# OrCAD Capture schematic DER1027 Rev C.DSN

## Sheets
1 PAGE2: size B
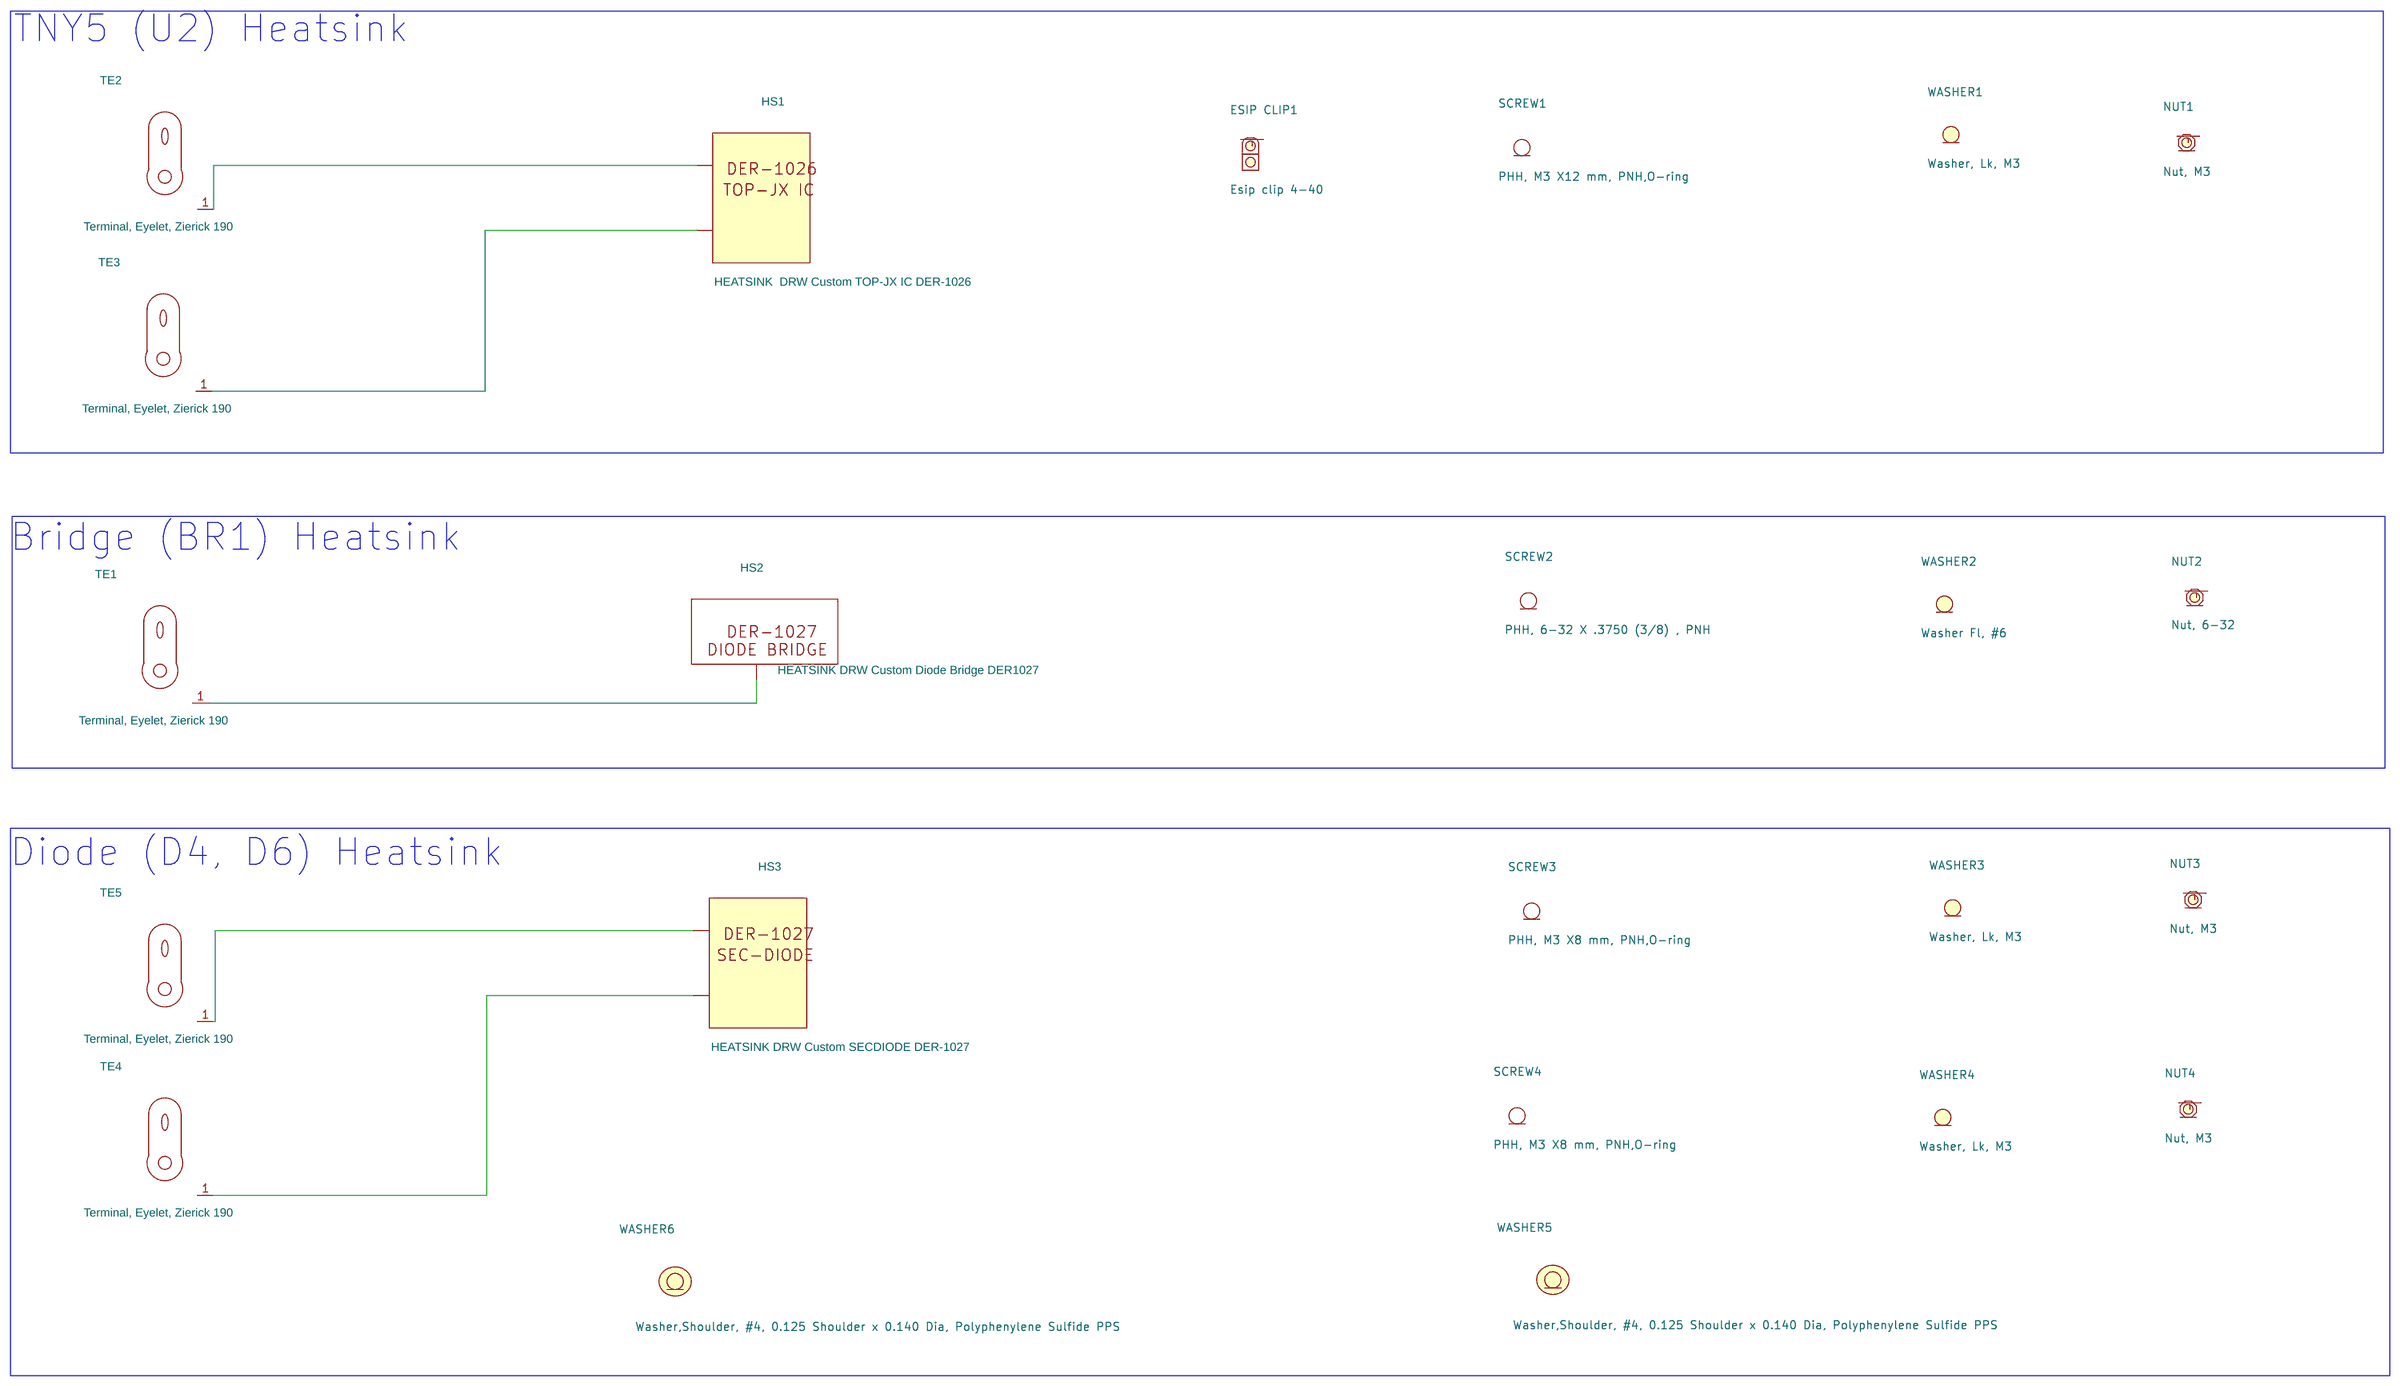
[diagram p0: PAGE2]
2 PAGE1: size C
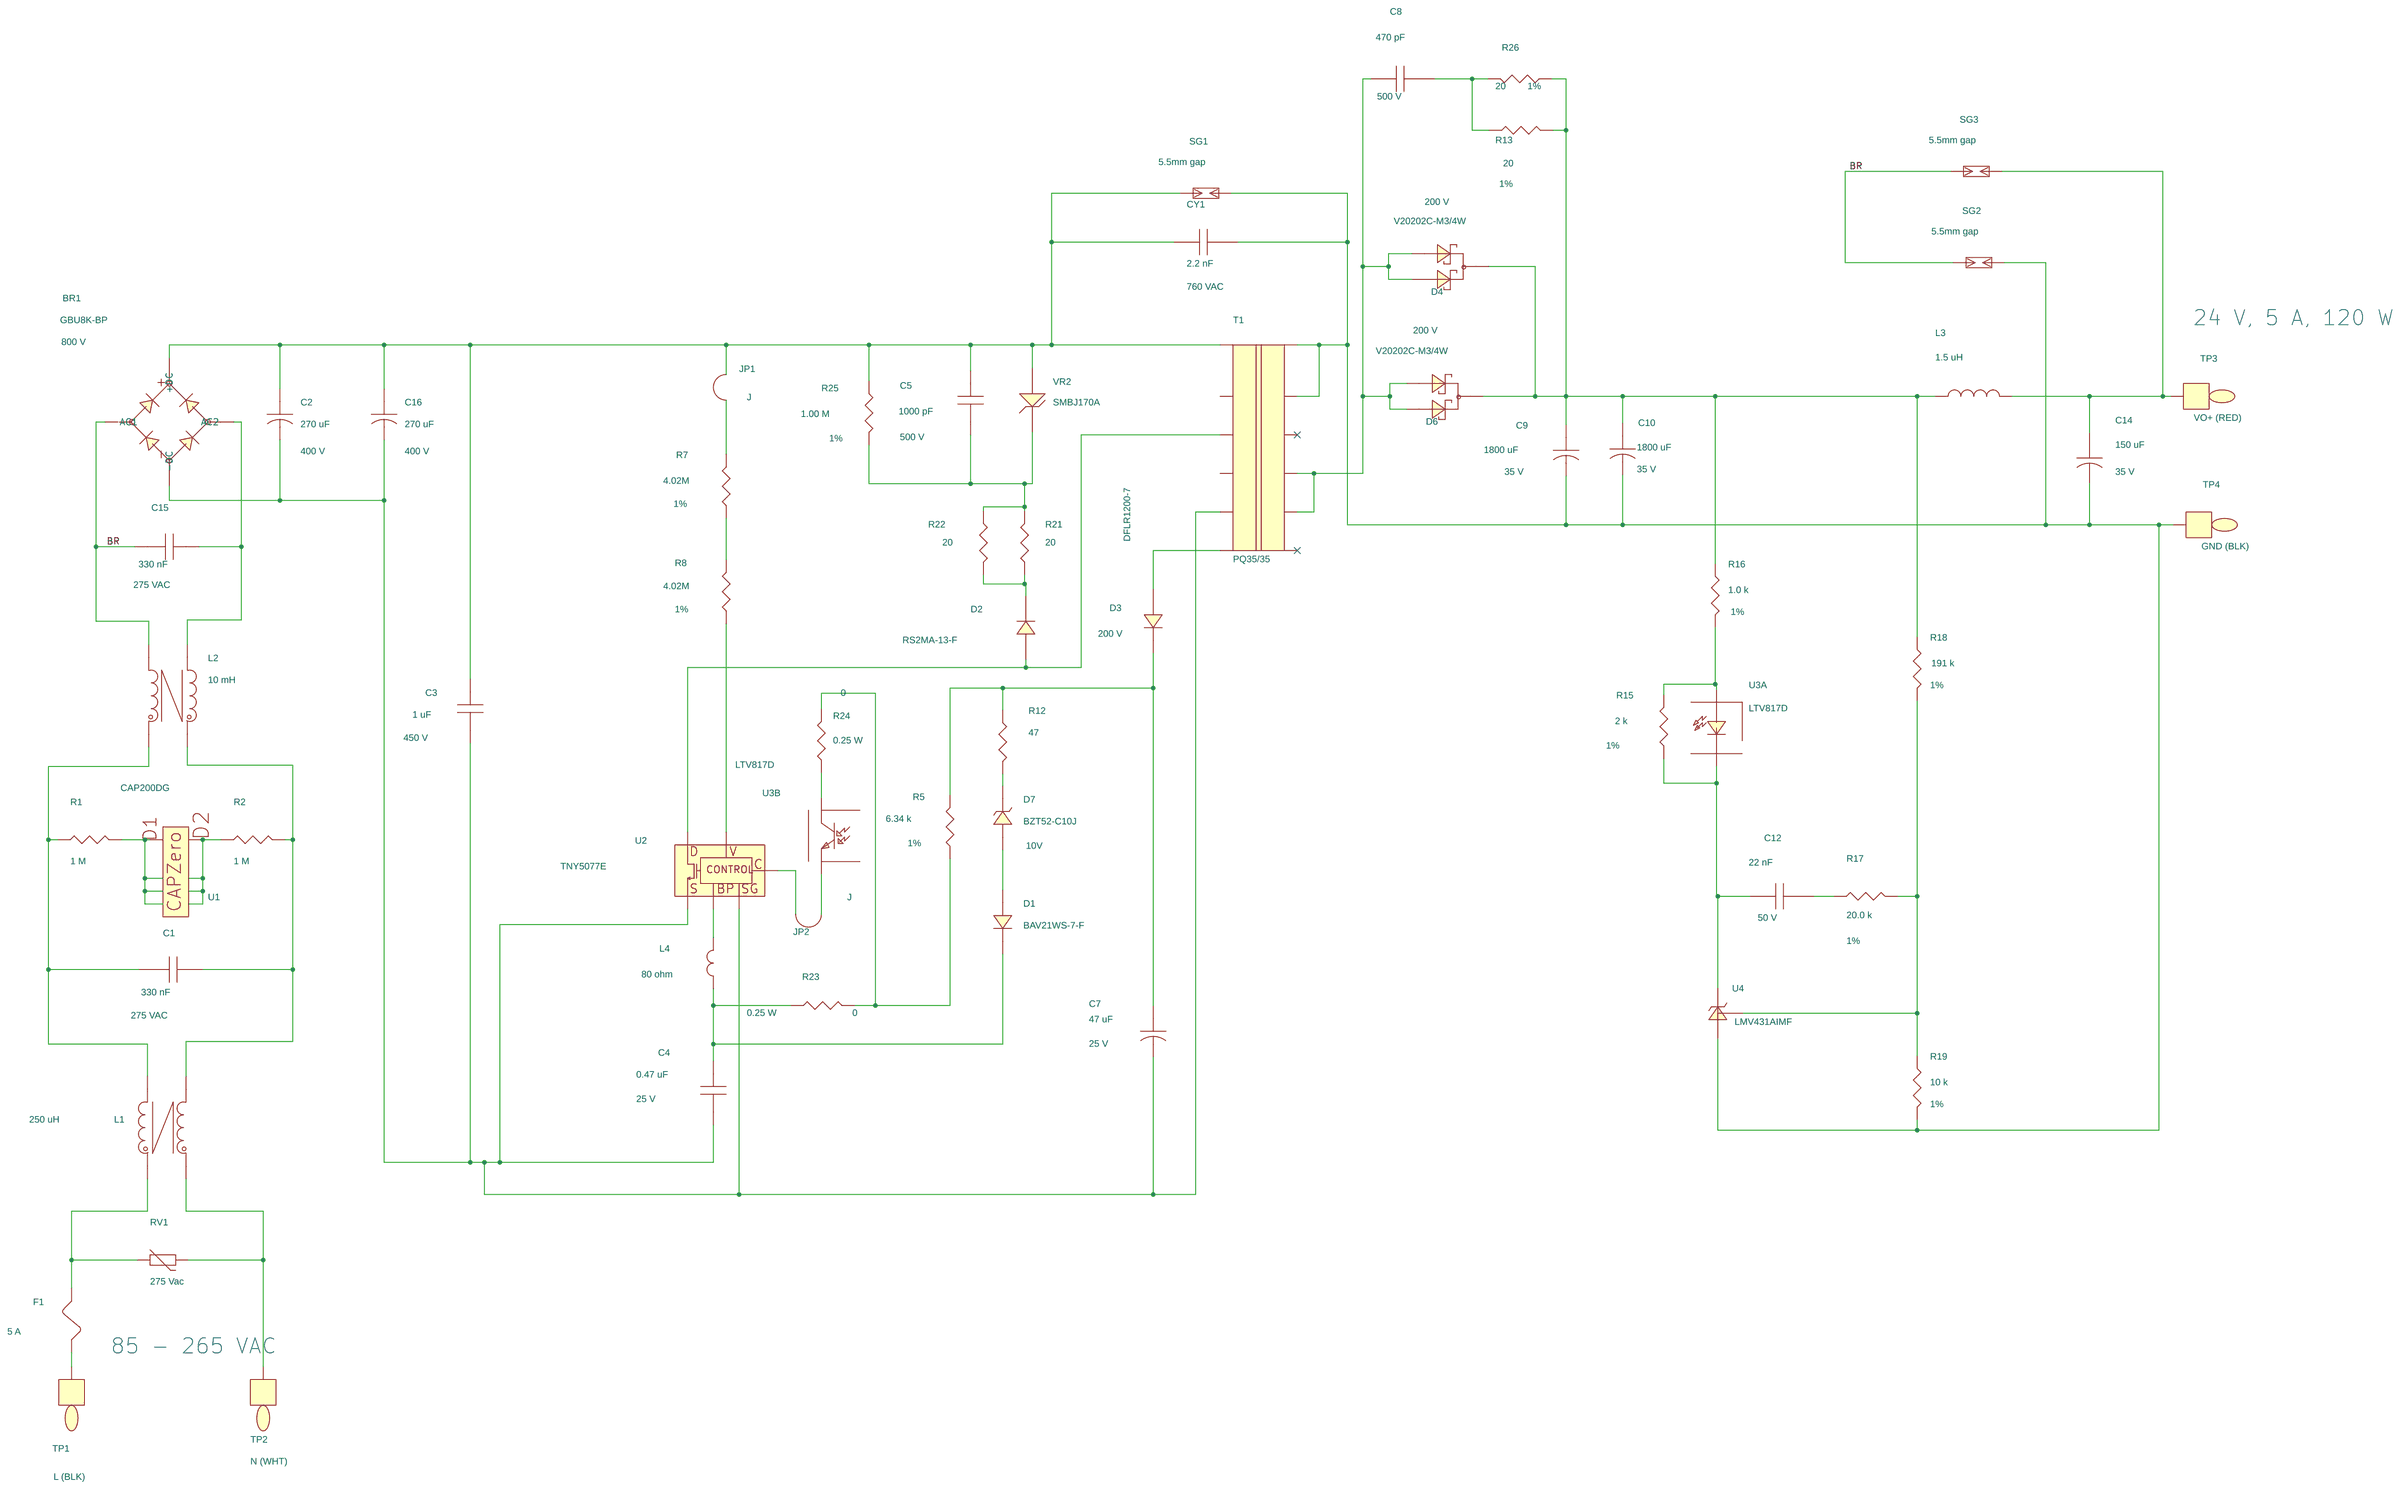
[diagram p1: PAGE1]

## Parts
sheet PAGE1
BR1  GBU8K-BP  [pidaxbridgegbu8]
C1  330 nF  [pinp_xcaprad15x8p5x14Hd040]
C2  270 uF  [pipolcapclyd985ls394086]
C3  1 uF  [pinpcaprad_12p6x9p2_ls10_d40]
C4  0.47 uF  [pismc0805]
C5  1000 pF  [pismc1206]
C7  47 uF  [pipolcapclyd200ls80030]
C8  470 pF  [pismc1206]
C9  1800 uF  [pipolcapclyd630ls300040]
C10  1800 uF  [pipolcapclyd630ls300040]
C12  22 nF  [pismc0805]
C14  150 uF  [pipolcapclyd320ls140030]
C15  330 nF  [pinp_xcaprad15x8p5x14Hd040]
C16  270 uF  [pipolcapclyd985ls394086]
CY1  2.2 nF  [pinpycaprad540x290ls400040]
D1  BAV21WS-7-F  [pismsod323]
D2  RS2MA-13-F  [pismdo214ac12]
D3  DFLR1200-7  [pismddflr120012]
D4  V20202C-M3/4W  [pidvto2203vf1]
D6  V20202C-M3/4W  [pidvto2203vf1]
D7  BZT52-C10J  [pi_sm_sod-123_12]
F1  5 A  [pi_rst_microfuse]
JP1  J  [pi_jumper500]
JP2  J  [pi_jumper500]
L1  250 uH  [pi_toroid_CMC13x6_5p8p_V]
L2  10 mH  [pi_toroid_balun_1]
L3  1.5 uH  [pi_choke_toko]
L4  80 ohm  [pismr0805]
R1  1 M  [pismr1206]
R2  1 M  [pismr1206]
R5  6.34 k  [pismr0805]
R7  4.02M  [pismr1206]
R8  4.02M  [pismr1206]
R12  47  [pismr1206]
R13  20  [pismr2010]
R15  2 k  [pismr1206]
R16  1.0 k  [pismr1206]
R17  20.0 k  [pismr1206]
R18  191 k  [pismr1206]
R19  10 k  [pismr1206]
R21  20  [pismr1206]
R22  20  [pismr1206]
R23  0  [pismr1206]
R24  0  [pismr1206]
R25  1.00 M  [pismr1206]
R26  20  [pismr2010]
RV1  275 Vac  [pidisc350x160ls210x140040]
SG1  5.5mm gap  [PI_SPARK_GAP_5p5MM]
SG2  5.5mm gap  [PI_SPARK_GAP_5p5MM]
SG3  5.5mm gap  [PI_SPARK_GAP_5p5MM]
T1  PQ35/35  [pi_bobbin_bpq35_35_12p]
TP1  L (BLK)  [pitpkeystone125x125]
TP2  N (WHT)  [pitpkeystone125x125]
TP3  VO+ (RED)  [pitpkeystone125x125]
TP4  GND (BLK)  [pitpkeystone125x125]
U1  CAP200DG  [pi_ic_smd_so8_capzero]
U2  TNY5077E  [piicesip76th]
U3  LTV817D  [pi_dip4]  (sections A,B)
U4  LMV431AIMF  [pismsot23132]
VR2  SMBJ170A  [pismdo214aa12]
sheet PAGE2
ESIP CLIP1  Esip clip 4-40
HS1  HEATSINK  DRW Custom TOP-JX IC DER-1026  [PI_hs_2P_DER-1026_TOP-JX_IC]
HS2  HEATSINK DRW Custom Diode Bridge DER1027  [PIHSDER1027DB]
HS3  HEATSINK DRW Custom SECDIODE DER-1027  [PI_hs_2P_DER-1027_SECDIODE]
NUT1  Nut, M3
NUT2  Nut, 6-32
NUT3  Nut, M3
NUT4  Nut, M3
SCREW1  PHH, M3 X12 mm, PNH,O-ring
SCREW2  PHH, 6-32 X .3750 (3/8) , PNH
SCREW3  PHH, M3 X8 mm, PNH,O-ring
SCREW4  PHH, M3 X8 mm, PNH,O-ring
TE1  Terminal, Eyelet, Zierick 190  [pi_zierick190_eyelet]
TE2  Terminal, Eyelet, Zierick 190  [pi_zierick190_eyelet]
TE3  Terminal, Eyelet, Zierick 190  [pi_zierick190_eyelet]
TE4  Terminal, Eyelet, Zierick 190  [pi_zierick190_eyelet]
TE5  Terminal, Eyelet, Zierick 190  [pi_zierick190_eyelet]
WASHER1  Washer, Lk, M3
WASHER2  Washer Fl, #6
WASHER3  Washer, Lk, M3
WASHER4  Washer, Lk, M3
WASHER5  Washer,Shoulder, #4, 0.125 Shoulder x 0.140 Dia, Polyphenylene Sulfide PPS
WASHER6  Washer,Shoulder, #4, 0.125 Shoulder x 0.140 Dia, Polyphenylene Sulfide PPS

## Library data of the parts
BR1 = DISCRETE_BRIDGE_+~~-: ALT_SYMBOLS: pidaxbridgegbu8_horz; Disp_Voltage: 800 V; FPLIST: pidaxbridgegbu8,pidaxbridgegbu8_horz; Part Number: 15-00347-00
C1 C15 = CAP_NP: ALT_SYMBOLS: pinp_xcaprad15x8p5x14Hd040H; Disp_Voltage: 275 VAC; FPLIST: pinp_xcaprad15x8p5x14Hd040,pinp_xcaprad15x8p5x14Hd040H; Part Number: 20-09095-00; ROOM: 1; Voltage: 275 VAC
C2 C16 = CAP_POL: Disp_Voltage: 400 V; Part Number: 20-02099-00; Voltage: 400 V
C3 = CAP_NP: ALT_SYMBOLS: pinpcaprad_12p6x9p2_ls10_d400H; Disp_Voltage: 450 V; FPLIST: pinpcaprad_12p6x9p2_ls10_d40,pinpcaprad_12p6x9p2_ls10_d40H; Part Number: 20-09184-00; Voltage: 450 V
C4 = CAP_NP: ALT_SYMBOLS: Unisem_RMCF0805UL; Disp_Voltage: 25 V; FPLIST: pismc0805,Unisem_RMCF0805UL; Part Number: 20-09182-00; Voltage: 25 V
C5 = CAP_NP: Disp_Voltage: 500 V; Part Number: 20-01980-00; Tol: 10; Voltage: 500 V
C7 = CAP_POL: ALT_SYMBOLS: pipolcapclyd200ls80030h; Disp_Voltage: 25 V; FPLIST: pipolcapclyd200ls80030,pipolcapclyd200ls80030h; Part Number: 20-00026-00; Tol: 20; Voltage: 25 V
C8 = CAP_NP: ALT_SYMBOLS: pismc1206_1; COMPGROUP: 2; Disp_Voltage: 500 V; FPLIST: pismc1206,pismc1206_1; Part Number: 20-08965-00; Tol: 10; Voltage: 500 V
C9 C10 = CAP_POL: ALT_SYMBOLS: pipolcapclyd630ls3000401000h; Disp_Voltage: 35 V; FPLIST: pipolcapclyd630ls300040,pipolcapclyd630ls3000401000h; PCB Editor PCBFP: pipolcapcyld400ls200040; Part Number: 20-00055-00; Voltage: 35 V
C12 = CAP_NP: ALT_SYMBOLS: Unisem_RMCF0805UL; Disp_Voltage: 50 V; FPLIST: pismc0805,Unisem_RMCF0805UL; PCB Editor PCBFP: pinpcaprad200x100200030; Part Number: 20-00225-00; Voltage: 50 V
C14 = CAP_POL: ALT_SYMBOLS: pipolcapclyd320ls140030430h; Disp_Voltage: 35 V; FPLIST: pipolcapclyd320ls140030,pipolcapclyd320ls140030430h,pipolcapclyd320ls140030430h; Part Number: 20-00691-00; Tol: 20; Voltage: 35 V
CY1 = CAP_NP: Disp_Voltage: 760 VAC; Part Number: 20-01427-00; Voltage: 760 VAC
D1 = DIODE: ALT_SYMBOLS: SOD323_UL_IPC,pismsod323_1; FPLIST: pismsod323,SOD323_UL_IPC,pismsod323_1; Part Number: 15-00385-00
D2 = DIODE: Part Number: 15-01059-00
D3 = DIODE: Disp_Voltage: 200 V; Part Number: 15-01019-00
D4 D6 = DS_DUAL_CK_AKA: ALT_SYMBOLS: pidvto2203,pidvto2203h; Disp_Voltage: 200 V; FPLIST: pidvto2203vf1,pidvto2203,pidvto2203h; Part Number: 15-02210-00
D7 = ZENER_DIODE: Disp_Voltage: 10V; FPLIST: pi_sm_sod-123_12,DIO_SOD-123; Part Number: 15-01910-00
F1 = FUSE: ALT_SYMBOLS: pirstmicrofusehoz; COMPGROUP: 1; FPLIST: pi_rst_microfuse,pirstmicrofusehoz; Part Number: 40-00052-00; ROOM: 1
JP1 JP2 = JUMPER_2: Part Number: 65-00044-00
L1 = TORRID_4P_12_34: Part Number: 30-00624-00; ROOM: 1
L2 = TORRID_4P_12_34: Part Number: 32-00016-00
L3 = INDUCTOR: ALT_SYMBOLS: pi_choke_toko_h; FPLIST: pi_choke_toko,pi_choke_toko_h; Part Number: 30-00387-00; Tol: 0.2
L4 = INDUCTOR_BEAD_2: Part Number: 30-00635-00
R1 R2 = R: Part Number: 05-01424-00
R5 = R: ALT_SYMBOLS: Unisem_RMCF0805UL; Disp_Tol: 1%; FPLIST: pismr0805,Unisem_RMCF0805UL; Part Number: 05-03383-00
R7 R8 = R: ALT_SYMBOLS: pismr1206_1; Disp_Power: 0.25 W; Disp_Tol: 1%; FPLIST: pismr1206,pismr1206_1; Part Number: 05-06470-00
R12 = R: Disp_Tol: 1%; Part Number: 05-03475-00
R13 R26 = R: Disp_Power: 1 W; Disp_Tol: 1%; PCB Editor PCBFP: pi14wvresd100ls100d030,pi14wvresd100ls200d030,pi14wresd100ls400d030,pi14wresd100ls500d030; Part Number: 05-06494-00
R15 = R: Disp_Tol: 1%; PCB Editor PCBFP: pi14wvresd100ls100d030,pi14wvresd100ls200d030,pi14wresd100ls400d030,pi14wresd100ls500d030; Part Number: 05-00222-00
R16 = R: Disp_Tol: 1%; PCB Editor PCBFP: pi14wvresd100ls100d030,pi14wvresd100ls200d030,pi14wresd100ls400d030,pi14wresd100ls500d030; Part Number: 05-00193-00
R17 = R: Disp_Tol: 1%; Part Number: 05-00318-00
R18 = R: Disp_Tol: 1%; PCB Editor PCBFP: pi14wvresd100ls100d030,pi14wvresd100ls200d030,pi14wresd100ls400d030,pi14wresd100ls500d030; Part Number: 05-00412-00
R19 = R: Disp_Tol: 1%; PCB Editor PCBFP: pi14wvresd100ls100d030,pi14wvresd100ls200d030,pi14wresd100ls400d030,pi14wresd100ls500d030; Part Number: 05-06571-00
R21 R22 = R: Part Number: 05-01311-00
R23 R24 = R: Disp_Power: 0.25 W; Part Number: 05-06696-00
R25 = R: Disp_Tol: 1%; Part Number: 05-03149-00
RV1 = VARISTOR: ALT_SYMBOLS: pi_disc_354x220_ls220x10_040_h; FPLIST: pidisc350x160ls210x140040,pi_disc_354x220_ls220x10_040_h; Part Number: 85-00015-00; ROOM: 1
SG1-SG3 = SPARK_GAP: Part Number: 66-00357-00
T1 = BPQ35_35_12P_GENERIC: Part Number: 25-00919-00
TP1 TP4 = TESTPOINT: Part Number: 35-00042-00
TP2 = TESTPOINT: Part Number: 35-00044-00
TP3 = TESTPOINT: Part Number: 35-00043-00
U1 = CAPZero: Part Number: 10-00958-00; ROOM: 1
U2 = TinySwitch-5E: Part Number: 10-01629-00
U3 = OPTO_A_B: COMPGROUP: 2; Part Number: 53-00019-00
U4 = TL431_SOT-23_RCA: Part Number: 45-00019-00
VR2 = DIODE_ZENER: Part Number: 16-00007-00
ESIP CLIP1 = EsipClip_4-40: Part Number: 60-00037-00
HS1 = hs_2P_DER-1026_TOP-JXIC: Part Number: 61-00357-00
HS2 = hs_1P_DER1027DB: Part Number: 61-00360-00
HS3 = hs_2P_DER-1027_SECDIODE: Part Number: 61-00361-00
NUT1 NUT3 NUT4 = NUT_HEX_M3: Part Number: 75-00055-00
NUT2 = NUT_HEX_6-32: Part Number: 75-00025-00
SCREW1 = SCR_M3: Part Number: 75-00214-00
SCREW2 = SCR_6-32: Part Number: 75-00009-00
SCREW3 SCREW4 = SCR_M3: Part Number: 75-00215-00
TE1-TE5 = TERM_EYLT: Part Number: 60-00016-00
WASHER1 WASHER3 WASHER4 = WASH_LOCK_M3: Part Number: 75-00059-00
WASHER2 = WASH_FLAT_6: Part Number: 75-00033-00
WASHER5 WASHER6 = WASH_SHLDR_4: Part Number: 75-00154-00

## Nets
BR: BR1.2(AC1) C15.2 L2.2 SG2.1 SG3.1
N1180522: BR1.1(+DC) C2.1 C3.1 C5.1 C16.1 CY1.1 JP1.2 R25.1 SG1.1 T1.1 VR2.2
N1180530: C9.2 C10.2 C14.2 CY1.2 R19.2 SG1.2 SG2.2 T1.11 T1.12 TP4.1 U4.3(A)
N1180572: C8.1 D4.1(A1) D4.3(A2) D6.1(A1) D6.3(A2) T1.8 T1.9
N1180580: C8.2 R13.2 R26.2
N1180772: C9.1 C10.1 D4.2(CATHODE) D6.2(CATHODE) L3.1 R13.1 R16.1 R18.1 R26.1
N1180800: C14.1 L3.2 SG3.2 TP3.1
N1180998: BR1.4(-DC) C2.2 C3.2 C4.2 C7.2 C16.2 T1.5 U2.4 U2.5
N1181144: R7.2 R8.1
N1181148: D2.2 T1.3 U2.7
N1181266: C7.1 D3.1 R5.1 R12.1
N1181270: R15.1 R16.2 U3.1(A)
N1181336: R17.1 R18.2 R19.1 U4.1(VREF)
N1181354: R8.2 U2.1
N1181442: C12.1 R15.2 U3.2(C) U4.2(C)
N1193924: D1.2 D7.2(ANODE)
N1193928: D7.1(CATHODE) R12.2
N11509583: C1.2 L1.4 L2.1 R1.1
N11509663: R1.2 U1.1(NC1) U1.2(D1) U1.3(NC2) U1.4(NC3)
N11509667: R2.1 U1.5(NC4) U1.6(NC5) U1.7(D2) U1.8(NC8)
N11509705: C1.1 L1.2 L2.3 R2.2
N11509765: F1.2 L1.3 RV1.1
N11509809: L1.1 RV1.2 TP2.1
N11514098: C12.2 R17.2
N11558446: BR1.3(AC2) C15.1 L2.4
N11565135: C5.2 R21.1 R22.1 R25.2 VR2.1
N11566250: F1.1 TP1.1
N11596495: D2.1 R21.2 R22.2
N11618490: D3.2 T1.6
N12576026: C4.1 D1.1 L4.1 R23.2
N12603395: JP1.1 R7.1
N12603572: JP2.2 U2.3
N12603576: JP2.1 U3.3(E)
N12614295: R5.2 R23.1 R24.1
N12614386: R24.2 U3.4(C)
N12619931: HS1.2 TE2.1
N12619939: HS1.1 TE3.1
N12620029: HS2.1 TE1.1
N12620119: HS3.2 TE5.1
N12620127: HS3.1 TE4.1
N12646059: L4.2 U2.2

Not connected (* = marked no-connect by the designer): T1 2 4 7* 10*

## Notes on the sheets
sheet 1
- TNY5 (U2) Heatsink
- Bridge (BR1) Heatsink
- Diode (D4, D6) Heatsink
sheet 2
- 24 V, 5 A, 120 W
- 85 - 265 VAC
